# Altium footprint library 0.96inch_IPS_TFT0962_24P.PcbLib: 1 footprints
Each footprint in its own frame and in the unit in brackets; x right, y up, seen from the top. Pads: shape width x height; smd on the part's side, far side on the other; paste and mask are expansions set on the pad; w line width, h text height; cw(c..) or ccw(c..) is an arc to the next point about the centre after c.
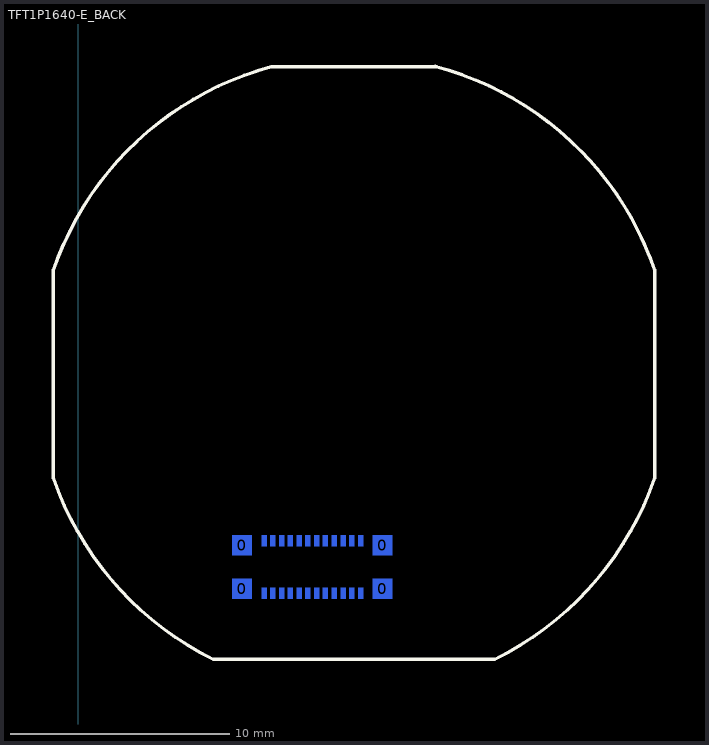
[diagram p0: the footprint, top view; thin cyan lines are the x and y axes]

## TFT1P1640-E_BACK [mm]
pads (28):
  rect 0.9x0.92 smd far side: 0(7.457,7.782) 0(7.457,9.762) 0(13.857,7.782) 0(13.857,9.762)
  rect 0.23x0.5 smd far side: 1(12.857,9.972) 2(12.457,9.972) 3(12.057,9.972) 4(11.657,9.972) 5(11.257,9.972) 6(10.857,9.972) 7(10.457,9.972) 8(10.057,9.972) 9(9.657,9.972) 10(9.257,9.972) 11(8.857,9.972) 12(8.457,9.972) 13(8.457,7.572) 14(8.857,7.572) 15(9.257,7.572) 16(9.657,7.572) 17(10.057,7.572) 18(10.457,7.572) 19(10.857,7.572) 20(11.257,7.572) 21(11.657,7.572) 22(12.057,7.572) 23(12.457,7.572) 24(12.857,7.572)
Top Overlay:
  lines w0.15: 6.132,4.572 18.982,4.572 ; 6.132,4.573 cw(c12.557,17.572) -1.143,12.822 -1.143,22.322 cw(c12.557,17.572) 8.777,31.571 ; 8.777,31.572 16.337,31.572 ; 16.261,31.591 cw(c12.557,17.572) 26.257,22.322 26.257,12.822 cw(c12.557,17.572) 18.982,4.573
Bottom Overlay:
  lines w0.15: 7.007,8.422 7.007,9.122 ; 8.056,7.672 8.206,7.672 ; 8.056,9.872 8.206,9.872 ; 13.108,7.672 13.258,7.672 ; 13.108,9.872 13.258,9.872 ; 14.307,8.422 14.307,9.122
